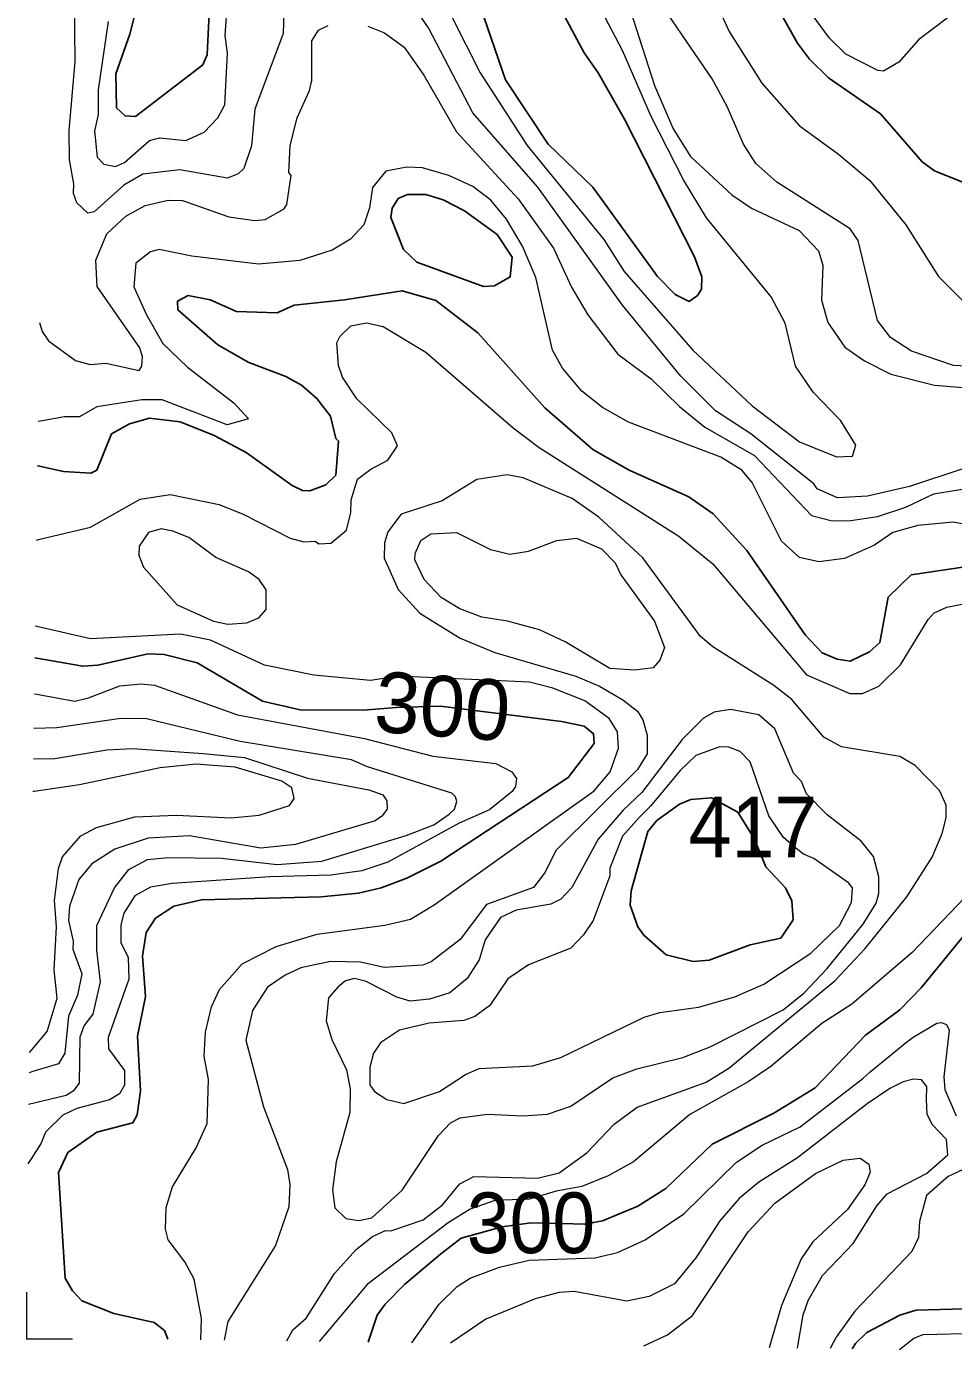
# Model space of a CAD drawing. Extents: x 673.6 to 698.9, y 7012 to 7040.1.
# Drawn here: x 673.644 to 674.868, y 7012.334 to 7014.081 of the extents above; entities that cross this region are included whole.
import ezdxf
from ezdxf.enums import TextEntityAlignment as Align

# ---------------------------------------------------------------- set-up
doc = ezdxf.new("R2010")
doc.units = 0
doc.header["$LTSCALE"] = 0.032
for name, color, linetype, lineweight in [('1', 7, 'Continuous', 25), ('2', 7, 'Continuous', 13), ('63', 7, 'Continuous', 13)]:
    doc.layers.add(name, color=color, linetype=linetype, lineweight=lineweight)
doc.layers.add('21', color=7, linetype='Continuous')
doc.layers.add('61', color=7, linetype='Continuous')

msp = doc.modelspace()

# ---------------------------------------------------------------- linework, layer by layer
at = {"layer": '1'}
for points in [[(674.5953, 7014.1779), (674.6622, 7014.0585), (674.678, 7014.0376), (674.7033, 7014.0127), (674.7719, 7013.9651), (674.827, 7013.9021)], [(673.7901, 7014.1066), (673.7811, 7014.0705), (673.7623, 7014.0182), (673.7634, 7013.9731), (673.7747, 7013.9625), (673.7886, 7013.962), (673.8773, 7014.0298), (673.8831, 7014.0432), (673.8867, 7014.1167)], [(674.2438, 7014.1061), (674.2768, 7014.0101), (674.3333, 7013.9254), (674.3923, 7013.8686), (674.4775, 7013.7508), (674.5007, 7013.7269), (674.5194, 7013.7178), (674.5303, 7013.7254), (674.5354, 7013.7339), (674.5362, 7013.7503), (674.5265, 7013.7767), (674.4341, 7013.9582), (674.3993, 7014.0195), (674.3807, 7014.0457), (674.3513, 7014.1007)], [(674.827, 7013.9021), (674.8432, 7013.8899), (674.8881, 7013.8719)], [(674.8893, 7013.3682), (674.8124, 7013.3569), (674.782, 7013.3275), (674.7709, 7013.2675), (674.7574, 7013.2552), (674.7317, 7013.2427), (674.7147, 7013.2453), (674.695, 7013.254), (674.6726, 7013.2774), (674.5953, 7013.389), (674.5511, 7013.4372), (674.5188, 7013.4596), (674.4402, 7013.4951), (674.3923, 7013.5222), (674.3287, 7013.5774), (674.2405, 7013.6763), (674.185, 7013.7188), (674.1404, 7013.7315), (674.0643, 7013.7198), (673.9977, 7013.7126), (673.9755, 7013.7027), (673.9217, 7013.7043), (673.8871, 7013.7199), (673.8581, 7013.7255), (673.8439, 7013.7181), (673.8443, 7013.7068), (673.897, 7013.6602), (673.9382, 7013.6369), (673.9867, 7013.6184), (674.0074, 7013.6071), (674.028, 7013.5897), (674.0457, 7013.5662), (674.0531, 7013.5366), (674.0565, 7013.5333), (674.0531, 7013.4885), (674.0396, 7013.4757), (674.0187, 7013.4677), (674.0091, 7013.4682), (673.9953, 7013.4745), (673.9345, 7013.5184), (673.8921, 7013.5407), (673.8474, 7013.5589), (673.8068, 7013.5634), (673.7804, 7013.5563), (673.7568, 7013.5431), (673.7375, 7013.4949), (673.7293, 7013.4909), (673.6936, 7013.4931), (673.6596, 7013.5006), (673.6591, 7013.5007)], [(673.6556, 7013.2472), (673.7188, 7013.236), (673.7389, 7013.2375), (673.805, 7013.2523), (673.8264, 7013.2515), (673.87, 7013.2404), (673.9559, 7013.19), (674.0056, 7013.1787), (674.0892, 7013.1779), (674.1324, 7013.1818), (674.1909, 7013.1835), (674.3509, 7013.1631), (674.3805, 7013.1568), (674.3931, 7013.147), (674.3941, 7013.1339), (674.3598, 7013.0891), (674.1916, 7012.9788), (674.1467, 7012.9564), (674.1127, 7012.9435), (674.0828, 7012.9364), (674.0334, 7012.9318), (673.8757, 7012.9277), (673.8391, 7012.9196), (673.8147, 7012.9037), (673.8025, 7012.8846), (673.7977, 7012.8533), (673.8017, 7012.8003), (673.7911, 7012.7478), (673.7952, 7012.6758), (673.7908, 7012.6439), (673.7849, 7012.6335), (673.7373, 7012.621), (673.6991, 7012.594), (673.6869, 7012.5676), (673.6958, 7012.4285), (673.7051, 7012.4116), (673.7178, 7012.3982), (673.7597, 7012.3816), (673.8132, 7012.3697), (673.8269, 7012.3592), (673.8309, 7012.3478)], [(674.0955, 7012.3439), (674.1075, 7012.3796), (674.1179, 7012.3941), (674.1436, 7012.42), (674.1909, 7012.4599), (674.2184, 7012.4812), (674.2724, 7012.496), (674.3105, 7012.5014), (674.3509, 7012.5004), (674.3817, 7012.4994), (674.4048, 7012.504), (674.4516, 7012.5235), (674.4887, 7012.5465), (674.5495, 7012.6052), (674.6309, 7012.6462), (674.6858, 7012.6797), (674.7519, 7012.7489), (674.7972, 7012.7826), (674.8254, 7012.8116), (674.8804, 7012.8789)], [(674.8827, 7012.3878), (674.8191, 7012.3862), (674.7974, 7012.3795), (674.7537, 7012.3568), (674.7387, 7012.3422), (674.7347, 7012.335)]]:
    msp.add_lwpolyline(points, dxfattribs=at)
for points in [[(674.2228, 7013.8373), (674.1945, 7013.8519), (674.1715, 7013.8587), (674.1473, 7013.8587), (674.1353, 7013.8534), (674.1272, 7013.8407), (674.1257, 7013.8284), (674.1421, 7013.7864), (674.1598, 7013.7695), (674.2478, 7013.7372), (674.2622, 7013.7383), (674.2831, 7013.75), (674.2856, 7013.7762), (674.266, 7013.8061)], [(674.6052, 7013.0088), (674.6203, 7012.9715), (674.6466, 7012.9434), (674.6549, 7012.9265), (674.6566, 7012.9012), (674.6401, 7012.8771), (674.5997, 7012.8683), (674.5455, 7012.8483), (674.5246, 7012.8464), (674.4891, 7012.8553), (674.4595, 7012.8813), (674.4516, 7012.8919), (674.4415, 7012.9205), (674.4427, 7012.9397), (674.4648, 7013.0179), (674.4767, 7013.0324), (674.5065, 7013.054), (674.5217, 7013.06), (674.5487, 7013.0624), (674.5835, 7013.0433)]]:
    msp.add_lwpolyline(points, close=True, dxfattribs=at)
at = {"layer": '2'}
for points in [[(674.9496, 7013.5197), (674.8101, 7013.4732), (674.7549, 7013.4605), (674.7152, 7013.4586), (674.6884, 7013.4704), (674.6841, 7013.4767), (674.6007, 7013.543), (674.5542, 7013.5731), (674.5081, 7013.6191), (674.4314, 7013.7127), (674.3194, 7013.8686), (674.2336, 7013.9666), (674.175, 7014.0787), (674.1357, 7014.1364)], [(674.9201, 7013.6304), (674.8681, 7013.6333), (674.813, 7013.6519), (674.7852, 7013.67), (674.768, 7013.6923), (674.7424, 7013.7983), (674.7319, 7013.8133), (674.6349, 7013.8749), (674.6073, 7013.8997), (674.591, 7013.9254), (674.5694, 7013.9752), (674.5497, 7014.0113), (674.463, 7014.1388)], [(673.9841, 7014.1001), (673.9834, 7014.0715), (673.9459, 7013.9716), (673.9414, 7013.923), (673.9313, 7013.893), (673.9241, 7013.8862), (673.9099, 7013.8802), (673.8468, 7013.8916), (673.7981, 7013.8857), (673.7732, 7013.8713), (673.734, 7013.8361), (673.7256, 7013.8342), (673.7108, 7013.8478), (673.7066, 7013.86), (673.7072, 7013.873), (673.7015, 7013.9044), (673.7007, 7013.9433), (673.7088, 7014.0343), (673.708, 7014.1175)], [(673.7524, 7014.0873), (673.7393, 7013.9972), (673.7392, 7013.964), (673.7344, 7013.943), (673.7377, 7013.9082), (673.7466, 7013.8988), (673.7619, 7013.8959), (673.7739, 7013.9009), (673.807, 7013.9303), (673.8199, 7013.9336), (673.8548, 7013.9303), (673.8789, 7013.9411), (673.8972, 7013.9601), (673.9063, 7013.9771), (673.9101, 7014.0453), (673.907, 7014.0688), (673.9097, 7014.1121)], [(674.2062, 7014.0935), (674.2434, 7014.0195), (674.3054, 7013.9234), (674.4065, 7013.7996), (674.4337, 7013.7574), (674.524, 7013.6533), (674.6024, 7013.58), (674.6651, 7013.5325), (674.7136, 7013.5125), (674.7349, 7013.5133), (674.7392, 7013.5279), (674.7194, 7013.5599), (674.6829, 7013.598), (674.6595, 7013.6321), (674.6462, 7013.6888), (674.6277, 7013.7236), (674.5423, 7013.8279), (674.5119, 7013.8782), (674.4692, 7013.962), (674.4314, 7014.0491), (674.3993, 7014.1099)], [(674.441, 7014.104), (674.4735, 7014.0028), (674.4981, 7013.9453), (674.5212, 7013.9092), (674.5757, 7013.8585), (674.6018, 7013.8409), (674.6646, 7013.8113), (674.6901, 7013.7845), (674.6957, 7013.7654), (674.6942, 7013.7192), (674.7023, 7013.6899), (674.7248, 7013.6573), (674.7506, 7013.6393), (674.7856, 7013.6215), (674.8432, 7013.6071), (675.0009, 7013.5943)], [(674.5575, 7014.1057), (674.5719, 7014.0738), (674.6153, 7014.006), (674.6646, 7013.95), (674.7166, 7013.9122), (674.758, 7013.8771), (674.8055, 7013.8187), (674.8485, 7013.7507), (674.8818, 7013.7172)], [(674.8616, 7014.0929), (674.8221, 7014.0632), (674.7962, 7014.0334), (674.776, 7014.0216), (674.7685, 7014.0226), (674.726, 7014.0439), (674.7045, 7014.0653), (674.6814, 7014.0967)], [(673.6617, 7013.6897), (673.6654, 7013.678), (673.6735, 7013.6656), (673.7094, 7013.6396), (673.7284, 7013.6345), (673.7491, 7013.636), (673.7932, 7013.6267), (673.7968, 7013.6321), (673.7976, 7013.6447), (673.794, 7013.6564), (673.7378, 7013.7373), (673.7361, 7013.7722), (673.7507, 7013.8068), (673.7756, 7013.8304), (673.8014, 7013.8444), (673.8315, 7013.8513), (673.8507, 7013.8511), (673.9118, 7013.8293), (673.946, 7013.8243), (673.9594, 7013.826), (673.9847, 7013.8398), (673.9884, 7013.8456), (673.994, 7013.8838), (673.9908, 7013.8879), (673.9924, 7013.9233), (674.002, 7013.96), (674.0183, 7013.9961), (674.021, 7014.0092), (674.0213, 7014.0617), (674.0302, 7014.0756), (674.0426, 7014.082)], [(674.0951, 7014.0812), (674.1173, 7014.0724), (674.143, 7014.0532), (674.1692, 7014.0162), (674.2122, 7013.9416), (674.2937, 7013.8533), (674.3401, 7013.7878), (674.3642, 7013.7364), (674.3856, 7013.7), (674.4252, 7013.6479), (674.4693, 7013.6153), (674.5065, 7013.5788), (674.54, 7013.5516), (674.6057, 7013.5142), (674.6808, 7013.435), (674.7082, 7013.4282), (674.7327, 7013.4283), (674.7678, 7013.4339), (674.8052, 7013.446), (674.8421, 7013.4635), (674.9387, 7013.4795)], [(674.955, 7013.4099), (674.8678, 7013.4264), (674.8211, 7013.4217), (674.7882, 7013.4126), (674.7641, 7013.396), (674.7245, 7013.3782), (674.6905, 7013.374), (674.6648, 7013.3795), (674.6412, 7013.4012), (674.6023, 7013.4788), (674.5889, 7013.4948), (674.5611, 7013.5123), (674.4391, 7013.5582), (674.4051, 7013.5778), (674.3778, 7013.5993), (674.3519, 7013.6296), (674.3391, 7013.6533), (674.3167, 7013.7494), (674.2993, 7013.7908), (674.2781, 7013.8262), (674.2577, 7013.8514), (674.2336, 7013.8696), (674.202, 7013.8837), (674.1675, 7013.8942), (674.1465, 7013.8949), (674.1188, 7013.8898), (674.1013, 7013.868), (674.0972, 7013.8411), (674.0899, 7013.819), (674.0722, 7013.8), (674.0479, 7013.7855), (674.0052, 7013.7716), (673.951, 7013.7668), (673.8626, 7013.7775), (673.8195, 7013.7864), (673.8083, 7013.7831), (673.7887, 7013.7684), (673.7863, 7013.7371), (673.803, 7013.7), (673.8246, 7013.6622), (673.8571, 7013.631), (673.9187, 7013.5832), (673.9375, 7013.5629), (673.9096, 7013.5549), (673.8235, 7013.5876), (673.7969, 7013.5877), (673.7376, 7013.5785), (673.7147, 7013.5655), (673.6946, 7013.5654), (673.6629, 7013.5597), (673.6599, 7013.5592)], [(673.6577, 7013.4027), (673.6622, 7013.4038), (673.7291, 7013.4198), (673.7948, 7013.4568), (673.834, 7013.4628), (673.899, 7013.4494), (673.9305, 7013.4369), (673.9927, 7013.4051), (674.0108, 7013.4003), (674.0257, 7013.401), (674.0306, 7013.3979), (674.0463, 7013.3986), (674.067, 7013.4159), (674.0728, 7013.4391), (674.073, 7013.4558), (674.0817, 7013.4829), (674.0991, 7013.4963), (674.1217, 7013.508), (674.1345, 7013.5271), (674.1267, 7013.5442), (674.0808, 7013.589), (674.0615, 7013.6175), (674.0566, 7013.6333), (674.0541, 7013.6629), (674.0588, 7013.6719), (674.0729, 7013.6853), (674.0932, 7013.6896), (674.1153, 7013.6845), (674.1715, 7013.6509), (674.2871, 7013.5509), (674.3213, 7013.5249), (674.5057, 7013.408), (674.5506, 7013.3711), (674.6743, 7013.2246), (674.7312, 7013.1999), (674.748, 7013.1999), (674.7698, 7013.2097), (674.7985, 7013.2378), (674.8347, 7013.2977), (674.8429, 7013.3064), (674.8594, 7013.3139), (674.8946, 7013.3213)], [(673.9881, 7012.3454), (673.9963, 7012.3602), (674.0137, 7012.3755), (674.0513, 7012.4344), (674.0797, 7012.4662), (674.1011, 7012.4833), (674.1186, 7012.4913), (674.1253, 7012.4907), (674.1682, 7012.5054), (674.1937, 7012.5251), (674.2164, 7012.5528), (674.2349, 7012.5627), (674.319, 7012.5605), (674.3478, 7012.5672), (674.3841, 7012.5939), (674.4201, 7012.6314), (674.4506, 7012.6539), (674.5416, 7012.6871), (674.5715, 7012.7055), (674.7119, 7012.8214), (674.7517, 7012.8637), (674.8067, 7012.9318), (674.8402, 7012.9841), (674.8534, 7013.0153), (674.8585, 7013.0358), (674.8584, 7013.0525), (674.8498, 7013.0719), (674.8177, 7013.105), (674.7974, 7013.1168), (674.7205, 7013.1298), (674.6969, 7013.1423), (674.6549, 7013.1921), (674.6311, 7013.2108), (674.5505, 7013.2616), (674.5344, 7013.2755), (674.4581, 7013.3792), (674.4002, 7013.4329), (674.3649, 7013.4575), (674.3, 7013.4847), (674.2791, 7013.4888), (674.239, 7013.4824), (674.1933, 7013.4546), (674.1392, 7013.4369), (674.1216, 7013.4134), (674.117, 7013.399), (674.1165, 7013.3786), (674.135, 7013.3373), (674.1639, 7013.306), (674.2172, 7013.273), (674.263, 7013.2541), (674.3698, 7013.223), (674.4011, 7013.2098), (674.4318, 7013.1919), (674.4509, 7013.1767), (674.4582, 7013.1653), (674.464, 7013.1452), (674.464, 7013.1206), (674.4511, 7013.1), (674.3437, 7012.9931), (674.3282, 7012.9628), (674.3137, 7012.9441), (674.2518, 7012.9218), (674.2168, 7012.8752), (674.1788, 7012.8457), (674.1679, 7012.8414), (674.1166, 7012.8382), (674.0853, 7012.8456), (674.0459, 7012.8463), (674.0068, 7012.838), (673.9862, 7012.8285), (673.9627, 7012.8124), (673.9428, 7012.7817), (673.9341, 7012.7425), (673.9574, 7012.6545), (673.9891, 7012.5719), (673.9923, 7012.5519), (673.9907, 7012.5226), (673.9734, 7012.4716), (673.9102, 7012.3711), (673.9057, 7012.3466)], [(673.8746, 7012.347), (673.8757, 7012.3751), (673.8659, 7012.427), (673.8537, 7012.45), (673.8315, 7012.4791), (673.8281, 7012.4931), (673.8288, 7012.5216), (673.8371, 7012.549), (673.8685, 7012.6003), (673.8829, 7012.6324), (673.8846, 7012.6906), (673.879, 7012.7215), (673.8807, 7012.7531), (673.8886, 7012.7865), (673.8992, 7012.8093), (673.9294, 7012.8431), (673.974, 7012.866), (674.0282, 7012.8825), (674.1177, 7012.8941), (674.1515, 7012.9022), (674.1825, 7012.921), (674.3937, 7013.0718), (674.415, 7013.0969), (674.4262, 7013.1278), (674.4247, 7013.1497), (674.4135, 7013.1669), (674.3817, 7013.1905), (674.3394, 7013.207), (674.3087, 7013.2152), (674.1362, 7013.223), (674.0985, 7013.2172), (674.024, 7013.2244), (673.9586, 7013.2373), (673.8876, 7013.2703), (673.8477, 7013.2786), (673.7291, 7013.2721), (673.658, 7013.2886), (673.6562, 7013.289)], [(673.6549, 7013.1997), (673.6555, 7013.1996), (673.7084, 7013.1899), (673.7266, 7013.1945), (673.7676, 7013.2102), (673.7957, 7013.213), (673.8136, 7013.2112), (673.9233, 7013.1718), (674.0907, 7013.1406), (674.1809, 7013.1173), (674.2643, 7013.1075), (674.2851, 7013.0966), (674.2914, 7013.0878), (674.2899, 7013.0775), (674.2855, 7013.0706), (674.2558, 7013.0464), (674.2159, 7013.0288), (674.1216, 7012.9775), (674.0871, 7012.9659), (674.0464, 7012.9601), (673.9658, 7012.9581), (673.8369, 7012.9492), (673.8082, 7012.9444), (673.7875, 7012.9331), (673.773, 7012.9101), (673.7689, 7012.8947), (673.7689, 7012.8714), (673.7787, 7012.8515), (673.7795, 7012.8231), (673.7525, 7012.7461), (673.7527, 7012.7311), (673.7737, 7012.7024), (673.7738, 7012.6832), (673.7674, 7012.6718), (673.754, 7012.6639), (673.711, 7012.6523), (673.6927, 7012.6435), (673.6695, 7012.6211), (673.6641, 7012.6066), (673.6506, 7012.5859), (673.6463, 7012.5793)], [(673.6474, 7012.6578), (673.6971, 7012.6698), (673.7075, 7012.6767), (673.7143, 7012.6859), (673.7154, 7012.747), (673.7207, 7012.7613), (673.7327, 7012.7769), (673.7424, 7012.8194), (673.7372, 7012.8613), (673.7376, 7012.8937), (673.7608, 7012.9436), (673.7797, 7012.968), (673.8043, 7012.9808), (673.831, 7012.9836), (673.902, 7012.9827), (673.9756, 7012.9746), (674.0344, 7012.9786), (674.1459, 7013.0126), (674.1823, 7013.0268), (674.2025, 7013.0409), (674.2096, 7013.0475), (674.2125, 7013.0575), (674.211, 7013.0637), (674.2062, 7013.0687), (674.0947, 7013.1031), (674.0734, 7013.1127), (673.9264, 7013.1367), (673.8031, 7013.1666), (673.7691, 7013.167), (673.6844, 7013.155), (673.6547, 7013.1538), (673.6543, 7013.1538)], [(673.6537, 7013.114), (673.654, 7013.114), (673.682, 7013.1143), (673.7508, 7013.1257), (673.7846, 7013.1274), (673.8779, 7013.1209), (673.9325, 7013.1158), (674.0157, 7013.0883), (674.0963, 7013.0731), (674.115, 7013.0664), (674.1203, 7013.0583), (674.1206, 7013.0475), (674.1135, 7013.0384), (674.1046, 7013.032), (673.9995, 7013.0006), (673.9539, 7012.996), (673.8599, 7013.0122), (673.8051, 7013.0093), (673.7613, 7012.9946), (673.7308, 7012.9752), (673.7135, 7012.9544), (673.7015, 7012.9194), (673.6999, 7012.9006), (673.7063, 7012.873), (673.7056, 7012.8628), (673.7178, 7012.8299), (673.712, 7012.8017), (673.6999, 7012.774), (673.6951, 7012.7254), (673.6868, 7012.7113), (673.653, 7012.701), (673.648, 7012.6995)], [(673.6484, 7012.7261), (673.6515, 7012.7298), (673.6718, 7012.7539), (673.6849, 7012.7981), (673.681, 7012.8354), (673.6841, 7012.8923), (673.6817, 7012.9268), (673.6867, 7012.9693), (673.692, 7012.9847), (673.7161, 7013.0122), (673.737, 7013.0231), (673.7876, 7013.0371), (673.8422, 7013.0395), (673.9146, 7013.0362), (673.9518, 7013.0395), (673.9917, 7013.0523), (673.998, 7013.0614), (673.995, 7013.0754), (673.9815, 7013.0843), (673.9201, 7013.1027), (673.8685, 7013.107), (673.8211, 7013.1019), (673.7143, 7013.0797), (673.6547, 7013.0708), (673.6531, 7013.0706)], [(674.8831, 7012.931), (674.8136, 7012.8582), (674.7342, 7012.7901), (674.6944, 7012.7644), (674.6269, 7012.7079), (674.5972, 7012.6876), (674.5202, 7012.6444), (674.446, 7012.5817), (674.4125, 7012.5633), (674.3776, 7012.5492), (674.3438, 7012.5433), (674.3086, 7012.5324), (674.263, 7012.5308), (674.2304, 7012.5192), (674.2012, 7012.5012), (674.0943, 7012.4199), (674.0307, 7012.3448)], [(674.1531, 7012.3431), (674.1894, 7012.3942), (674.2132, 7012.4172), (674.2301, 7012.4282), (674.2691, 7012.443), (674.3079, 7012.4519), (674.3947, 7012.4551), (674.4246, 7012.4624), (674.4611, 7012.4787), (674.5122, 7012.5132), (674.5817, 7012.5813), (674.6158, 7012.6037), (674.6657, 7012.6283), (674.7486, 7012.6917), (674.7584, 7012.7008), (674.7919, 7012.7279), (674.8043, 7012.7386), (674.8152, 7012.7463), (674.8464, 7012.7649), (674.8525, 7012.7659), (674.8589, 7012.7632), (674.8625, 7012.7557), (674.8553, 7012.6941), (674.8568, 7012.6775), (674.8717, 7012.6424)], [(674.6623, 7012.336), (674.6698, 7012.3798), (674.6766, 7012.3989), (674.6955, 7012.4319), (674.7358, 7012.4741), (674.7669, 7012.5236), (674.7805, 7012.5398), (674.8325, 7012.5663), (674.8609, 7012.5912), (674.8591, 7012.6115), (674.8401, 7012.6313), (674.8337, 7012.6449), (674.8326, 7012.664), (674.8329, 7012.6812), (674.8262, 7012.6903), (674.8155, 7012.6911), (674.8016, 7012.6873), (674.7842, 7012.6785), (674.7543, 7012.6586), (674.6623, 7012.5871), (674.6114, 7012.555), (674.5854, 7012.5337), (674.56, 7012.5042), (674.5279, 7012.455), (674.4999, 7012.4209), (674.4667, 7012.404), (674.4369, 7012.3978), (674.3676, 7012.4109), (674.3478, 7012.4093), (674.3162, 7012.401), (674.2511, 7012.3742), (674.2044, 7012.3424)], [(674.4596, 7012.3389), (674.4905, 7012.3534), (674.5239, 7012.3791), (674.597, 7012.4895), (674.6323, 7012.5273), (674.6862, 7012.5663), (674.7224, 7012.5842), (674.7451, 7012.5866), (674.7567, 7012.5786), (674.7581, 7012.5684), (674.7513, 7012.5517), (674.7283, 7012.5191), (674.6824, 7012.4764), (674.6672, 7012.4539), (674.6413, 7012.3922), (674.6247, 7012.3365)], [(674.901, 7012.581), (674.8613, 7012.5625), (674.8325, 7012.5376), (674.8232, 7012.5032), (674.8219, 7012.4821), (674.8132, 7012.4634), (674.7379, 7012.3848), (674.7132, 7012.3506), (674.7055, 7012.3354)], [(674.7969, 7012.3341), (674.816, 7012.3491), (674.8282, 7012.354), (674.9, 7012.3558)]]:
    msp.add_lwpolyline(points, dxfattribs=at)
for points in [[(673.9378, 7013.3609), (673.8945, 7013.3797), (673.8589, 7013.4061), (673.8379, 7013.4142), (673.8222, 7013.4173), (673.8055, 7013.4126), (673.7934, 7013.3945), (673.7929, 7013.3827), (673.7992, 7013.3667), (673.8434, 7013.317), (673.8912, 7013.2957), (673.9103, 7013.2918), (673.9354, 7013.2933), (673.9511, 7013.3001), (673.9609, 7013.3108), (673.961, 7013.3368), (673.9516, 7013.3505)], [(674.3445, 7013.4021), (674.3704, 7013.4051), (674.4035, 7013.391), (674.4216, 7013.3728), (674.429, 7013.3569), (674.4735, 7013.2957), (674.4868, 7013.2607), (674.4805, 7013.2442), (674.4718, 7013.2338), (674.4471, 7013.2309), (674.4147, 7013.2333), (674.3558, 7013.2684), (674.3217, 7013.284), (674.2795, 7013.2956), (674.2458, 7013.3008), (674.2165, 7013.312), (674.1921, 7013.327), (674.1697, 7013.3504), (674.157, 7013.3766), (674.1575, 7013.3851), (674.1651, 7013.402), (674.1781, 7013.4111), (674.2122, 7013.4125), (674.2569, 7013.3902), (674.2827, 7013.384), (674.3073, 7013.3878)], [(674.4184, 7012.6926), (674.4502, 7012.7048), (674.511, 7012.7196), (674.547, 7012.7339), (674.6435, 7012.7826), (674.6706, 7012.8047), (674.7013, 7012.837), (674.749, 7012.8954), (674.7663, 7012.9232), (674.7697, 7012.9363), (674.7697, 7012.9581), (674.7625, 7012.985), (674.7464, 7013.0052), (674.7014, 7013.0398), (674.6741, 7013.0678), (674.6677, 7013.0838), (674.6571, 7013.0949), (674.6326, 7013.1534), (674.6114, 7013.1719), (674.5739, 7013.1791), (674.5524, 7013.1755), (674.5383, 7013.1677), (674.5101, 7013.1392), (674.4569, 7013.0693), (674.4323, 7013.0463), (674.3991, 7013.0079), (674.3644, 7012.944), (674.3498, 7012.9287), (674.3368, 7012.9222), (674.2911, 7012.9141), (674.2701, 7012.9046), (674.2499, 7012.8751), (674.2423, 7012.8484), (674.2263, 7012.8241), (674.2034, 7012.805), (674.1767, 7012.7964), (674.1512, 7012.7939), (674.1336, 7012.7992), (674.0929, 7012.82), (674.0774, 7012.8238), (674.0656, 7012.8209), (674.056, 7012.813), (674.0434, 7012.7983), (674.0401, 7012.7678), (674.0478, 7012.7432), (674.0671, 7012.7034), (674.072, 7012.6784), (674.0712, 7012.647), (674.0532, 7012.5818), (674.0483, 7012.5448), (674.0515, 7012.5213), (674.066, 7012.5071), (674.0831, 7012.5046), (674.1005, 7012.5078), (674.1403, 7012.5443), (674.1882, 7012.6166), (674.2041, 7012.6332), (674.2169, 7012.6401), (674.253, 7012.645), (674.3, 7012.6426), (674.3324, 7012.6447), (674.3631, 7012.6554)], [(674.4598, 7012.7727), (674.4804, 7012.779), (674.5317, 7012.786), (674.5796, 7012.7999), (674.6178, 7012.8164), (674.6799, 7012.8575), (674.7178, 7012.8938), (674.7337, 7012.9243), (674.7348, 7012.9437), (674.7297, 7012.9503), (674.6837, 7012.9825), (674.6704, 7012.9882), (674.6601, 7012.9961), (674.644, 7013.0101), (674.6244, 7013.0385), (674.6, 7013.1099), (674.5866, 7013.1235), (674.5703, 7013.1298), (674.5585, 7013.1291), (674.5279, 7013.1182), (674.5076, 7013.0986), (674.4683, 7013.0513), (674.4539, 7013.0368), (674.4315, 7013.0118), (674.4148, 7012.9696), (674.4145, 7012.9595), (674.3925, 7012.9006), (674.3799, 7012.8815), (674.3632, 7012.8639), (674.3074, 7012.8419), (674.2801, 7012.8233), (674.2563, 7012.7883), (674.2363, 7012.7736), (674.222, 7012.7684), (674.1761, 7012.765), (674.1368, 7012.7559), (674.1118, 7012.7389), (674.1027, 7012.7254), (674.0976, 7012.7067), (674.0977, 7012.6837), (674.104, 7012.6747), (674.1202, 7012.6642), (674.1425, 7012.6591), (674.1896, 7012.6747), (674.224, 7012.697), (674.2419, 7012.7049), (674.313, 7012.7087), (674.3499, 7012.7196)]]:
    msp.add_lwpolyline(points, close=True, dxfattribs=at)
at = {"layer": '63'}
msp.add_lwpolyline([(673.6445, 7012.41), (673.6445, 7012.3484), (673.7052, 7012.3484)], dxfattribs=at)

# ---------------------------------------------------------------- texts
at = {"layer": '21', "width": 0.95}
msp.add_text('417', height=0.08, dxfattribs=at).set_placement((674.5186, 7012.9839))
at = {"layer": '61'}
msp.add_text('300', height=0.08, rotation=355.815, dxfattribs=at).set_placement((674.1909, 7013.1435), align=Align.CENTER)
at = {"layer": '61', "width": 0.95}
msp.add_text('300', height=0.08, dxfattribs=at).set_placement((674.3105, 7012.4614), align=Align.CENTER)

doc.saveas('drawing.dxf')
